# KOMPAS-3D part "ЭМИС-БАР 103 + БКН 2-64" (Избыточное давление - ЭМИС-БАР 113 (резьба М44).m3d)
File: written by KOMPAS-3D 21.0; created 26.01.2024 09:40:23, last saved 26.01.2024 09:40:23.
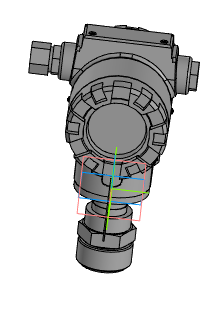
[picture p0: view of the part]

Document properties: Автор: Admin; Организация: office.local; Полное имя файла: S:\Эмис\Инженерный\Расходомеры и фильтры\Задачи\Черненков А.А\ЭМИС-БАР\3D-модели для сайта\Датчики избыточного давления ЭМИС-БАР\Компоненты\ЭМИС-БАР 113 (резьба М44).m3d

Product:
- Part/product: ЭМИС-БАР 103 + БКН 2-64
    Масса: 4.324951
    Форматы листов документа: A4

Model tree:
1. Операция без истории:1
